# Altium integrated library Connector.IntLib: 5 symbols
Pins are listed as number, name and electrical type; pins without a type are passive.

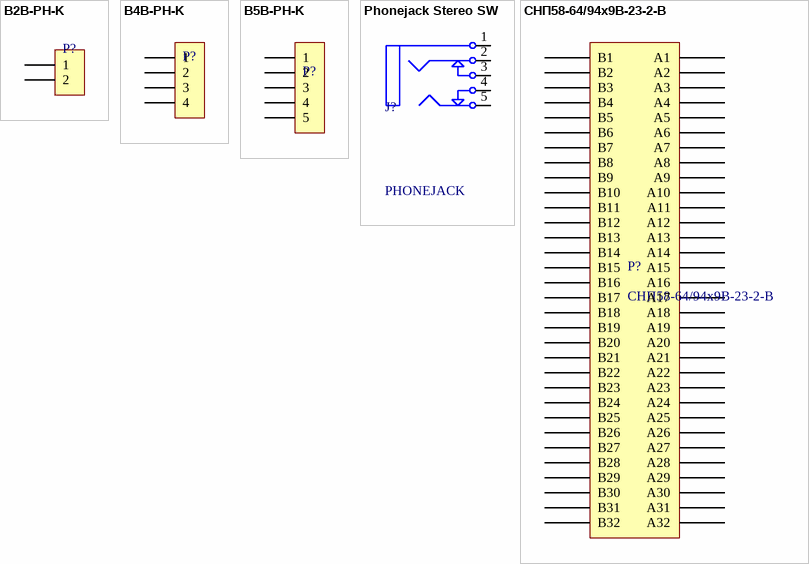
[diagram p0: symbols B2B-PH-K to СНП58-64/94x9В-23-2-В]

## B2B-PH-K
designator P?
2.0mm pitch/Disconnectable Crimp style connectors, 2 pins
footprint B2B-PH-K
pins: 1, 2

## B4B-PH-K
designator P?
2.0mm pitch/Disconnectable Crimp style connectors, 4 pins
footprint B4B-PH-K
pins: 1, 2, 3, 4

## B5B-PH-K
designator P?
2.0mm pitch/Disconnectable Crimp style connectors, 5 pins
footprint B5B-PH-K
pins: 1, 2, 3, 4, 5

## Phonejack Stereo SW
designator J?, comment PHONEJACK
3-Conductor Jack with 2 break contacts (normals) and 2 auxiliary make contacts
signal-integrity model Connector
footprint PHONEJACK_3.5 (Generic 3.5 mm phone jack)
pins: 1, 2, 3, 4, 5

## СНП58-64/94x9В-23-2-В
designator P?
footprint snp58
pins: A1, A2, A3, A4, A5, A6, A7, A8, A9, A10, A11, A12, A13, A14, A15, A16, A17, A18, A19, A20, A21, A22, A23, A24, A25, A26, A27, A28, A29, A30, A31, A32, B1, B2, B3, B4, B5, B6, B7, B8, B9, B10, B11, B12, B13, B14, B15, B16, B17, B18, B19, B20, B21, B22, B23, B24, B25, B26, B27, B28, B29, B30, B31, B32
